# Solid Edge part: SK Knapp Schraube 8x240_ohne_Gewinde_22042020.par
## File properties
Author: langejürgent
Template: Normal.par
Last saved by: fknapp
Revision: 34
Application: Solid Edge
Username: fknapp
Genauigkeit: 0,99
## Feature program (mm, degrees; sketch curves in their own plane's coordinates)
sketch for "unnamed RevolvedProtrusion 1" plane through (0, 0, 0) normal (1, 0, 0) x-axis (0, 1, 0)
  line (0, 49.2048) -> (7.5, 49.2048)
  arc centre (7.5, 48.7048) radius 0.5 from (7.5, 49.2048) to (7.9949, 48.7762) cw
  line (4, 44.7814) -> (7.9949, 48.7762)
  line (4, 44.7814) -> (4, 39.7814)
  line (4, 39.7814) -> (3, 37.6369)
  line (3, 37.6369) -> (3, 36.5914)
  line (3, 36.5914) -> (4, 36.5914)
  line (4, 36.5914) -> (4, -185.0516)
  line (0, -190.7952) -> (4, -185.0516)
revolve "unnamed RevolvedProtrusion 1" add full turn 360 deg about sketch line (0, 49.2048) -> (0, -190.7952)
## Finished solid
Body 1: solid body, 9 faces, 8 edges, 1 vertex.
  Faces by surface: cone 3, cylinder 3, plane 2, torus 1
  Edges by curve: circle 8
Bounding box of the edges (mm; curved faces can reach further): 15.990 x 15.990 x 234.256, from (-7.9949, -7.9949, -185.0516) to (7.9949, 7.9949, 49.2048).
Cylindrical faces by radius (mm): R3 x1, R4 x2
Conical faces (half-angle, radius in mm at the cone's reference point): 25 deg R4 x1, 34.8543 deg R4 x1, 45 deg R7.9949 x1
Toroidal faces (ring radius, tube radius in mm): R7.5 r0.5 x1
Planar faces by outward normal: +z 2
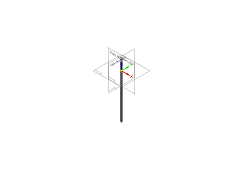
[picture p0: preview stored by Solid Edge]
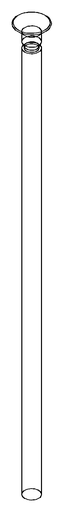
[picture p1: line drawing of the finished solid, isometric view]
